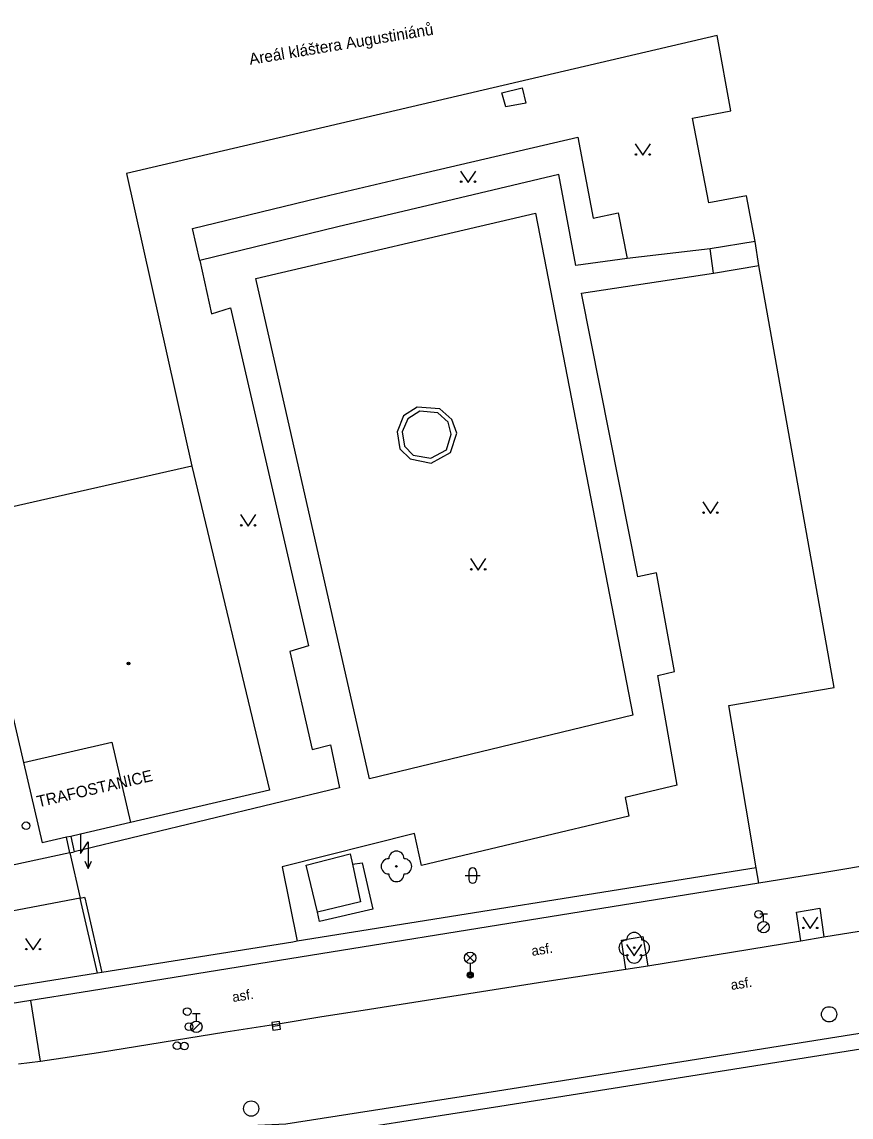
# Model space of a CAD drawing. Extents: x -600309 to -598967, y -1161267 to -1160292.
# Drawn here: x -599236.1 to -599181.8, y -1161124.2 to -1161052.5 of the extents above; entities that cross this region are included whole.
import ezdxf

# ---------------------------------------------------------------- set-up
doc = ezdxf.new("R2010")
doc.units = 0
for name, color, linetype in [('Level 10', 7, 'Continuous'), ('Level 11', 7, 'Continuous'), ('Level 22', 7, 'Continuous'), ('Level 27', 7, 'Continuous'), ('Level 28', 7, 'Continuous'), ('Level 31', 7, 'Continuous'), ('Level 33', 7, 'Continuous'), ('Level 36', 7, 'Continuous'), ('Level 39', 7, 'Continuous'), ('Level 40', 7, 'Continuous'), ('Level 41', 7, 'Continuous'), ('Level 5', 7, 'Continuous'), ('Level 54', 7, 'Continuous'), ('Level 7', 7, 'Continuous'), ('Level 8', 7, 'Continuous')]:
    doc.layers.add(name, color=color, linetype=linetype)

msp = doc.modelspace()

# ---------------------------------------------------------------- linework, layer by layer
at = {"layer": 'Level 10'}
for points in [[(-599183.6, -1161112.4), (-599173.38, -1161110.75)], [(-599185.1, -1161112.65), (-599183.6, -1161112.4)], [(-599195.12, -1161114.29), (-599185.1, -1161112.65)], [(-599234.9, -1161120.54), (-599231.09, -1161119.96), (-599222.76, -1161118.62), (-599219.08, -1161118.04), (-599216.61, -1161117.64), (-599213.35, -1161117.13), (-599201.87, -1161115.32), (-599196.56, -1161114.51)], [(-599196.56, -1161114.51), (-599195.12, -1161114.29)], [(-599236.34, -1161120.7199), (-599234.9, -1161120.54)]]:
    msp.add_lwpolyline(points, dxfattribs=at)
at = {"layer": 'Level 11'}
for points in [[(-599193.21, -1161102.46), (-599196.62, -1161103.27), (-599196.37, -1161104.5), (-599209.94, -1161107.72), (-599210.4, -1161105.63), (-599219.07, -1161107.81), (-599218.08, -1161112.69)], [(-599232.98, -1161106.9), (-599236.81, -1161107.72)], [(-599119.42, -1161109.21), (-599119.94, -1161107.92), (-599131.98, -1161110.59), (-599141.68, -1161112.37), (-599147.5578, -1161113.2881), (-599152.18, -1161114.01), (-599167.25, -1161116.49), (-599181.79, -1161118.82), (-599204.9699, -1161122.5), (-599218.82, -1161124.6599), (-599221.59, -1161124.8), (-599225.08, -1161124.96), (-599236.06, -1161126.61)], [(-599232.3, -1161109.86), (-599240.81, -1161111.47)], [(-599236.06, -1161126.61), (-599235.9099, -1161127.6), (-599225.55, -1161125.98), (-599221.58, -1161125.8), (-599218.77, -1161125.6599), (-599204.81, -1161123.48), (-599181.6, -1161119.8), (-599169.59, -1161117.88), (-599167.12, -1161117.49), (-599152.01, -1161114.99), (-599147.39, -1161114.27), (-599141.52, -1161113.35), (-599132.1, -1161111.64), (-599125.56, -1161110.17)], [(-599185.1, -1161112.65), (-599185.4, -1161110.77), (-599183.86, -1161110.52), (-599183.6, -1161112.4)], [(-599196.56, -1161114.51), (-599196.86, -1161112.61), (-599195.46, -1161112.38), (-599195.12, -1161114.29)], [(-599234.9, -1161120.54), (-599235.52, -1161116.56)]]:
    msp.add_lwpolyline(points, dxfattribs=at)
at = {"layer": 'Level 22'}
for centre in [(-599211.59, -1161107.78), (-599196.02, -1161113.11)]:
    msp.add_circle(centre, 0.05, dxfattribs=at)
for centre, start, end in [((-599212.09, -1161107.78), 90, 270), ((-599211.59, -1161107.28), 0, 180), ((-599211.09, -1161107.78), 270, 90), ((-599211.59, -1161108.28), 180, 0), ((-599196.02, -1161112.61), 0, 180), ((-599196.52, -1161113.11), 90, 270), ((-599195.52, -1161113.11), 270, 90), ((-599196.02, -1161113.61), 180, 0)]:
    msp.add_arc(centre, 0.5, start, end, dxfattribs=at)
at = {"layer": 'Level 27'}
msp.add_line((-599219.708, -1161118.2515), (-599219.212, -1161118.1883), dxfattribs=at)
msp.add_lwpolyline([(-599219.6764, -1161118.4995), (-599219.1804, -1161118.4363), (-599219.2436, -1161117.9403), (-599219.7396, -1161118.0035)], close=True, dxfattribs=at)
for centre in [(-599183.26, -1161117.4699), (-599221.1, -1161123.64)]:
    msp.add_circle(centre, 0.5, dxfattribs=at)
at = {"layer": 'Level 28'}
for p, q in [((-599187.8, -1161110.895), (-599187.3, -1161110.895)), ((-599187.55, -1161111.395), (-599187.55, -1161110.895)), ((-599187.808, -1161112.042), (-599187.278, -1161111.512)), ((-599224.94, -1161117.415), (-599224.44, -1161117.415)), ((-599224.69, -1161117.915), (-599224.69, -1161117.415)), ((-599224.948, -1161118.562), (-599224.418, -1161118.032))]:
    msp.add_line(p, q, dxfattribs=at)
for centre, radius in [((-599235.84, -1161105.12), 0.25), ((-599187.55, -1161111.77), 0.375), ((-599225.18, -1161118.28), 0.25), ((-599224.69, -1161118.29), 0.375)]:
    msp.add_circle(centre, radius, dxfattribs=at)
at = {"layer": 'Level 31'}
for centre in [(-599187.88, -1161110.92), (-599225.29, -1161117.29), (-599225.95, -1161119.53), (-599225.4699, -1161119.55)]:
    msp.add_circle(centre, 0.25, dxfattribs=at)
at = {"layer": 'Level 33'}
for p, q in [((-599207.025, -1161114.04), (-599206.495, -1161113.51)), ((-599207.025, -1161113.51), (-599206.495, -1161114.04)), ((-599206.76, -1161114.15), (-599206.76, -1161114.9))]:
    msp.add_line(p, q, dxfattribs=at)
for centre, radius in [((-599206.76, -1161113.775), 0.375), ((-599206.76, -1161114.9), 0.2), ((-599206.76, -1161114.9), 0.1445), ((-599206.76, -1161114.9), 0.0876)]:
    msp.add_circle(centre, radius, dxfattribs=at)
at = {"layer": 'Level 36'}
for p, q in [((-599207.096, -1161108.386), (-599206.096, -1161108.386)), ((-599206.846, -1161108.136), (-599206.846, -1161108.636)), ((-599206.346, -1161108.136), (-599206.346, -1161108.636))]:
    msp.add_line(p, q, dxfattribs=at)
for points in [[(-599195.96, -1161060.4699), (-599195.46, -1161061.2199), (-599194.96, -1161060.4699)], [(-599207.4, -1161062.25), (-599206.9, -1161063), (-599206.4, -1161062.25)], [(-599191.53, -1161083.92), (-599191.03, -1161084.67), (-599190.53, -1161083.92)], [(-599221.8, -1161084.75), (-599221.3, -1161085.5), (-599220.8, -1161084.75)], [(-599206.73, -1161087.63), (-599206.23, -1161088.38), (-599205.73, -1161087.63)], [(-599232.28, -1161105.68), (-599232.28, -1161106.93), (-599231.78, -1161106.18), (-599231.78, -1161107.93)], [(-599231.999, -1161107.441), (-599231.78, -1161107.93), (-599231.561, -1161107.441)], [(-599184.99, -1161111.11), (-599184.49, -1161111.86), (-599183.99, -1161111.11)], [(-599235.87, -1161112.5), (-599235.37, -1161113.25), (-599234.87, -1161112.5)], [(-599196.52, -1161112.9), (-599196.02, -1161113.65), (-599195.52, -1161112.9)]]:
    msp.add_lwpolyline(points, dxfattribs=at)
for centre in [(-599195.9102, -1161061.1697), (-599195.0108, -1161061.1697), (-599207.3502, -1161062.9498), (-599206.4508, -1161062.9498), (-599191.4802, -1161084.6198), (-599190.5808, -1161084.6198), (-599221.7502, -1161085.4498), (-599220.8508, -1161085.4498), (-599206.6802, -1161088.3298), (-599205.7808, -1161088.3298), (-599184.9402, -1161111.8098), (-599184.0408, -1161111.8098), (-599235.8202, -1161113.1998), (-599234.9208, -1161113.1998), (-599196.4702, -1161113.5998), (-599195.5708, -1161113.5998)]:
    msp.add_circle(centre, 0.05, dxfattribs=at)
for centre, start, end in [((-599206.5957, -1161108.1363), 0, 180), ((-599206.5957, -1161108.6363), 180, 0)]:
    msp.add_arc(centre, 0.25, start, end, dxfattribs=at)
at = {"layer": 'Level 39'}
for radius in [0.09, 0.0398]:
    msp.add_circle((-599229.13, -1161094.49), radius, dxfattribs=at)
at = {"layer": 'Level 5'}
for points in [[(-599190.59, -1161053.37), (-599229.26, -1161062.42)], [(-599189.7, -1161058.31), (-599190.59, -1161053.37)], [(-599192.21, -1161058.79), (-599189.7, -1161058.31)], [(-599191.13, -1161064.33), (-599192.21, -1161058.79)], [(-599229.26, -1161062.42), (-599224.99, -1161081.58)], [(-599188.67, -1161063.88), (-599191.13, -1161064.33)], [(-599188.1, -1161066.87), (-599188.67, -1161063.88)], [(-599187.86, -1161068.44), (-599188.1, -1161066.87)], [(-599182.93, -1161096.07), (-599187.86, -1161068.44)], [(-599224.99, -1161081.58), (-599238, -1161084.53)], [(-599224.99, -1161081.58), (-599219.89, -1161102.8)], [(-599239.74, -1161084.95), (-599236, -1161100.98), (-599234.78, -1161106.24)], [(-599189.82, -1161097.25), (-599182.93, -1161096.07)], [(-599188.03, -1161107.88), (-599188.69, -1161103.96), (-599189.82, -1161097.25)], [(-599236, -1161100.98), (-599230.22, -1161099.64), (-599229, -1161104.91)], [(-599219.89, -1161102.8), (-599229, -1161104.91), (-599232.28, -1161105.68), (-599232.9, -1161105.82), (-599233.19, -1161105.88), (-599234.78, -1161106.24)], [(-599168.95, -1161105.74), (-599183.67, -1161108.2)], [(-599187.86, -1161108.89), (-599188.03, -1161107.88)], [(-599183.67, -1161108.2), (-599187.86, -1161108.89)]]:
    msp.add_lwpolyline(points, dxfattribs=at)
at = {"layer": 'Level 54'}
for points in [[(-599204.68, -1161057.12), (-599203.35, -1161056.81)], [(-599204.42, -1161058.04), (-599204.68, -1161057.12)], [(-599203.35, -1161056.81), (-599203.12, -1161057.81)], [(-599203.12, -1161057.81), (-599204.42, -1161058.04)], [(-599209.65, -1161062.34), (-599199.71, -1161060.03)], [(-599199.71, -1161060.03), (-599198.71, -1161065.34)], [(-599215.96, -1161063.84), (-599209.65, -1161062.34)], [(-599200.95, -1161062.48), (-599209.14, -1161064.43)], [(-599199.84, -1161068.44), (-599200.95, -1161062.48)], [(-599224.94, -1161066.01), (-599215.96, -1161063.84)], [(-599220.8, -1161069.29), (-599202.48, -1161065)], [(-599209.14, -1161064.43), (-599215.42, -1161065.9)], [(-599202.48, -1161065), (-599196.11, -1161097.87)], [(-599198.71, -1161065.34), (-599197.08, -1161064.98)], [(-599197.08, -1161064.98), (-599196.49, -1161067.9699)], [(-599224.4699, -1161068.1), (-599224.94, -1161066.01)], [(-599215.42, -1161065.9), (-599224.4699, -1161068.1)], [(-599188.1, -1161066.87), (-599191.04, -1161067.34)], [(-599191.04, -1161067.34), (-599196.49, -1161067.9699)], [(-599190.82, -1161068.94), (-599191.04, -1161067.34)], [(-599224.4699, -1161068.1), (-599223.7, -1161071.6)], [(-599196.49, -1161067.9699), (-599199.84, -1161068.44)], [(-599190.82, -1161068.94), (-599187.86, -1161068.44)], [(-599213.36, -1161102.04), (-599220.8, -1161069.29)], [(-599199.48, -1161070.25), (-599190.82, -1161068.94)], [(-599195.78, -1161088.82), (-599199.48, -1161070.25)], [(-599223.7, -1161071.6), (-599222.46, -1161071.21)], [(-599222.46, -1161071.21), (-599217.34, -1161093.35)], [(-599210.23, -1161077.7199), (-599211.12, -1161078.27)], [(-599210.05, -1161077.98), (-599210.85, -1161078.4699)], [(-599208.75, -1161077.83), (-599210.23, -1161077.7199)], [(-599208.88, -1161078.09), (-599210.05, -1161077.98)], [(-599207.96, -1161078.52), (-599208.75, -1161077.83)], [(-599211.12, -1161078.27), (-599211.54, -1161079.33)], [(-599210.85, -1161078.4699), (-599211.21, -1161079.33)], [(-599208.2, -1161078.69), (-599208.88, -1161078.09)], [(-599208.01, -1161079.4699), (-599208.2, -1161078.69)], [(-599207.64, -1161079.42), (-599207.96, -1161078.52)], [(-599211.54, -1161079.33), (-599211.36, -1161080.43)], [(-599211.21, -1161079.33), (-599211.07, -1161080.26)], [(-599208.06, -1161080.69), (-599207.64, -1161079.42)], [(-599208.31, -1161080.5), (-599208.01, -1161079.4699)], [(-599211.36, -1161080.43), (-599210.69, -1161081.09)], [(-599211.07, -1161080.26), (-599210.49, -1161080.86)], [(-599210.49, -1161080.86), (-599209.34, -1161081.06)], [(-599209.34, -1161081.06), (-599208.31, -1161080.5)], [(-599209.32, -1161081.39), (-599208.06, -1161080.69)], [(-599210.69, -1161081.09), (-599209.32, -1161081.39)], [(-599194.57, -1161088.56), (-599195.78, -1161088.82)], [(-599193.38, -1161095.02), (-599194.57, -1161088.56)], [(-599217.34, -1161093.35), (-599218.57, -1161093.7199)], [(-599218.57, -1161093.7199), (-599217.11, -1161100.12)], [(-599194.48, -1161095.28), (-599193.38, -1161095.02)], [(-599193.21, -1161102.46), (-599194.48, -1161095.28)], [(-599196.11, -1161097.87), (-599213.36, -1161102.04)], [(-599217.11, -1161100.12), (-599215.9, -1161099.83)], [(-599215.9, -1161099.83), (-599215.31, -1161102.64)], [(-599215.31, -1161102.64), (-599232.7, -1161106.84)], [(-599217.5, -1161107.71), (-599214.61, -1161106.96)], [(-599214.61, -1161106.96), (-599214.46, -1161107.64)], [(-599216.76, -1161110.77), (-599217.5, -1161107.71)], [(-599214.46, -1161107.64), (-599213.83, -1161107.56)], [(-599214.46, -1161107.64), (-599213.94, -1161110.1)], [(-599213.83, -1161107.56), (-599213.13, -1161110.58)], [(-599213.94, -1161110.1), (-599216.76, -1161110.77)], [(-599216.62, -1161111.39), (-599216.76, -1161110.77)], [(-599213.13, -1161110.58), (-599216.62, -1161111.39)]]:
    msp.add_lwpolyline(points, dxfattribs=at)
at = {"layer": 'Level 7'}
for points in [[(-599232.98, -1161106.9), (-599233.19, -1161105.88)], [(-599232.9, -1161105.82), (-599232.7, -1161106.84)], [(-599232.98, -1161106.9), (-599232.7, -1161106.84)], [(-599188.03, -1161107.88), (-599218.08, -1161112.69)], [(-599187.86, -1161108.89), (-599232.24, -1161116.05), (-599235.52, -1161116.56)], [(-599232.3, -1161109.86), (-599232.01, -1161109.79)], [(-599231.1599, -1161114.78), (-599232.3, -1161109.86)], [(-599232.01, -1161109.79), (-599231.97, -1161109.94), (-599231.9, -1161110.24), (-599230.87, -1161114.73)], [(-599218.37, -1161112.74), (-599230.87, -1161114.73)], [(-599218.08, -1161112.69), (-599218.37, -1161112.74)], [(-599231.1599, -1161114.78), (-599240.02, -1161116.19)], [(-599230.87, -1161114.73), (-599231.1599, -1161114.78)], [(-599235.52, -1161116.56), (-599240.54, -1161117.38)]]:
    msp.add_lwpolyline(points, dxfattribs=at)
at = {"layer": 'Level 8'}
msp.add_lwpolyline([(-599232.98, -1161106.9), (-599232.3, -1161109.86)], dxfattribs=at)

# ---------------------------------------------------------------- texts
at = {"layer": 'Level 40'}
for p in [(-599202.7, -1161113.65), (-599189.65, -1161115.88), (-599222.29, -1161116.67)]:
    msp.add_text('asf.', height=0.65, rotation=9, dxfattribs=at).set_placement(p)
at = {"layer": 'Level 41'}
for s, rotation, p in [('Areál kláštera Augustiniánů', 9.36, (-599221.17, -1161055.3)), ('TRAFOSTANICE', 13, (-599235.04, -1161103.92))]:
    msp.add_text(s, height=0.75, rotation=rotation, dxfattribs=at).set_placement(p)

doc.saveas('drawing.dxf')
